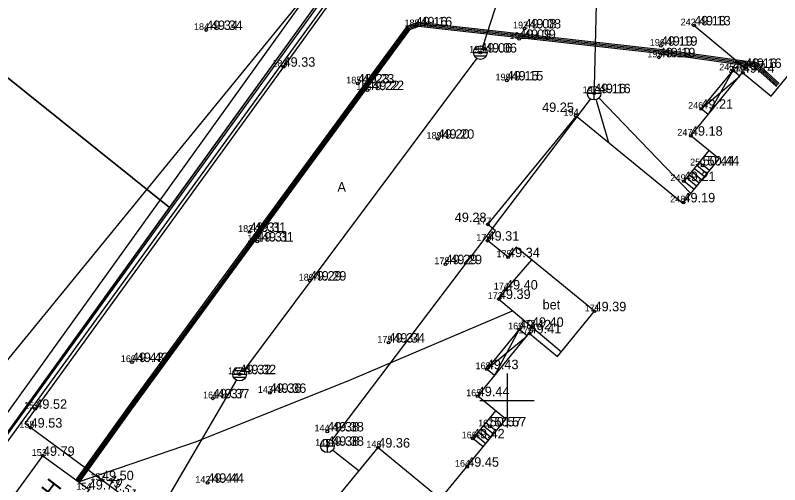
# Model space of a CAD drawing. Extents: x 640876 to 641418, y 6455595 to 6456085.
# Drawn here: x 641063.8 to 641120.1, y 6455893.8 to 6455928.4 of the extents above; entities that cross this region are included whole.
import ezdxf

# ---------------------------------------------------------------- set-up
doc = ezdxf.new("R2010")
doc.units = 0
for name, color, linetype in [('AED', 7, 'Continuous'), ('HOONE', 7, 'Continuous'), ('HOONEDET', 7, 'Continuous'), ('KKAEV', 7, 'Continuous'), ('KORGUS', 7, 'Continuous'), ('KTRASS', 7, 'Continuous'), ('MOOTKORG', 7, 'Continuous'), ('MOOTMPUNKT', 7, 'Continuous'), ('MOOTNR', 7, 'Continuous'), ('MOOTPIIR', 7, 'Continuous'), ('MPKAABEL', 7, 'Continuous'), ('PIIR', 7, 'Continuous'), ('PUU', 7, 'Continuous'), ('SKKAEV', 7, 'Continuous'), ('TEE', 7, 'Continuous'), ('VORK', 7, 'Continuous')]:
    doc.layers.add(name, color=color, linetype=linetype)

msp = doc.modelspace()

# ---------------------------------------------------------------- linework, layer by layer
at = {"layer": 'AED'}
for points in [[(641063.184, 6455882.915), (641067.225, 6455888.43), (641061.101, 6455894.64), (641102.569, 6455951.872), (641103.756, 6455952.954), (641094.123, 6455962.857), (641083.796, 6455973.39)], [(641113.788, 6455927.654), (641117.539, 6455924.523)]]:
    msp.add_lwpolyline(points, dxfattribs=at)
at = {"layer": 'HOONE'}
for p, q in [((641117.148, 6455923.919), (641116.636, 6455924.339)), ((641114.827, 6455921.087), (641114.315, 6455921.507)), ((641101.484, 6455904.77), (641100.904, 6455905.245)), ((641099.081, 6455901.837), (641098.503, 6455902.311)), ((641063.825, 6455893.209), (641065.802, 6455895.917))]:
    msp.add_line(p, q, dxfattribs=at)
for points in [[(641080.933, 6455884.842), (641090.509, 6455896.528), (641095.11, 6455892.757), (641099.913, 6455898.619), (641097.838, 6455900.32), (641101.638, 6455904.958), (641103.721, 6455903.251), (641106.446, 6455906.577), (641100.678, 6455911.304), (641100.074, 6455910.567), (641098.571, 6455911.798), (641099.157, 6455912.513), (641098.578, 6455912.988), (641105.114, 6455920.964), (641112.947, 6455914.545), (641115.628, 6455917.817), (641113.546, 6455919.523), (641117.357, 6455924.174), (641119.462, 6455922.449), (641148.038, 6455957.319)], [(641116.636, 6455924.339), (641114.315, 6455921.507)], [(641100.904, 6455905.245), (641098.503, 6455902.311)], [(641065.802, 6455895.917), (641069.2, 6455893.436), (641067.212, 6455890.725)]]:
    msp.add_lwpolyline(points, dxfattribs=at)
at = {"layer": 'HOONEDET'}
for p, q in [((641114.871, 6455918.437), (641113.022, 6455916.18)), ((641114.729, 6455916.72), (641113.972, 6455917.34)), ((641114.919, 6455916.952), (641114.162, 6455917.572)), ((641114.158, 6455916.024), (641113.402, 6455916.644)), ((641114.349, 6455916.256), (641113.592, 6455916.876)), ((641114.539, 6455916.488), (641113.782, 6455917.108)), ((641113.778, 6455915.56), (641113.022, 6455916.18)), ((641113.968, 6455915.792), (641113.212, 6455916.412)), ((641099.152, 6455899.243), (641097.483, 6455897.206)), ((641099.005, 6455897.51), (641098.243, 6455898.134)), ((641099.195, 6455897.742), (641098.434, 6455898.366)), ((641098.434, 6455896.814), (641097.673, 6455897.438)), ((641098.624, 6455897.046), (641097.863, 6455897.67)), ((641098.814, 6455897.278), (641098.053, 6455897.902)), ((641098.244, 6455896.582), (641097.483, 6455897.206))]:
    msp.add_line(p, q, dxfattribs=at)
for points in [[(641114.315, 6455921.507), (641117.148, 6455923.919)], [(641116.636, 6455924.339), (641114.827, 6455921.087)], [(641098.503, 6455902.311), (641101.484, 6455904.77)], [(641100.904, 6455905.245), (641099.081, 6455901.837)]]:
    msp.add_lwpolyline(points, dxfattribs=at)
at = {"layer": 'KKAEV'}
for p, q in [((641106.418, 6455922.157), (641106.418, 6455923.157)), ((641105.918, 6455922.657), (641106.918, 6455922.657)), ((641086.767, 6455896.162), (641086.767, 6455897.162)), ((641086.267, 6455896.662), (641087.267, 6455896.662))]:
    msp.add_line(p, q, dxfattribs=at)
for centre in [(641106.418, 6455922.657), (641086.767, 6455896.662)]:
    msp.add_circle(centre, 0.5, dxfattribs=at)
at = {"layer": 'KORGUS'}
for centre in [(641077.833, 6455927.316), (641093.266, 6455927.587), (641101.29, 6455927.431), (641113.788, 6455927.654), (641100.901, 6455926.656), (641111.34, 6455926.154), (641098.035, 6455925.649), (641111.186, 6455925.303), (641117.539, 6455924.523), (641089.001, 6455923.375), (641099.978, 6455923.596), (641089.722, 6455922.885), (641106.418, 6455922.657), (641105.062, 6455921.006), (641094.893, 6455919.299), (641114.416, 6455917.326), (641098.578, 6455912.988), (641081.035, 6455912.426), (641081.594, 6455911.72), (641095.469, 6455910.049), (641085.472, 6455908.84), (641091.271, 6455904.268), (641072.368, 6455902.834), (641080.295, 6455901.942), (641078.324, 6455900.158), (641082.516, 6455900.562), (641098.726, 6455898.089), (641086.759, 6455897.718), (641086.767, 6455896.662), (641090.509, 6455896.528), (641077.93, 6455893.935)]:
    msp.add_circle(centre, 0.1, dxfattribs=at)
at = {"layer": 'KTRASS'}
for points in [[(641107.089, 6455950.372), (641106.418, 6455923.157)], [(641104.971, 6455947.019), (641098.222, 6455926.122)], [(641090.812, 6455936.841), (641051.218, 6455888.362)], [(641097.769, 6455925.247), (641080.648, 6455902.296)], [(641106.114, 6455922.218), (641087.069, 6455897.06)], [(641106.771, 6455922.304), (641113.54, 6455915.269)], [(641106.562, 6455922.141), (641107.489, 6455919.018)], [(641080.069, 6455901.529), (641068.888, 6455882.4)], [(641087.159, 6455896.351), (641089.102, 6455894.81)]]:
    msp.add_lwpolyline(points, dxfattribs=at)
at = {"layer": 'MOOTMPUNKT'}
for centre in [(641077.833, 6455927.316), (641093.266, 6455927.587), (641101.29, 6455927.431), (641113.788, 6455927.654), (641100.901, 6455926.656), (641111.34, 6455926.154), (641098.035, 6455925.649), (641111.186, 6455925.303), (641083.533, 6455924.608), (641117.539, 6455924.523), (641116.636, 6455924.339), (641117.367, 6455924.166), (641089.001, 6455923.375), (641099.978, 6455923.596), (641089.722, 6455922.885), (641106.418, 6455922.657), (641114.315, 6455921.507), (641094.893, 6455919.299), (641113.546, 6455919.523), (641114.416, 6455917.326), (641113.022, 6455916.18), (641112.997, 6455914.606), (641081.035, 6455912.426), (641081.594, 6455911.72), (641098.56, 6455911.784), (641100.074, 6455910.567), (641095.469, 6455910.049), (641085.472, 6455908.84), (641099.924, 6455908.183), (641099.398, 6455907.484), (641106.446, 6455906.577), (641100.904, 6455905.245), (641101.832, 6455905.433), (641101.655, 6455904.944), (641091.271, 6455904.268), (641072.368, 6455902.834), (641080.295, 6455901.942), (641098.503, 6455902.311), (641078.324, 6455900.158), (641082.516, 6455900.562), (641097.838, 6455900.32), (641065.242, 6455899.388), (641064.893, 6455897.998), (641098.726, 6455898.089), (641086.759, 6455897.718), (641097.483, 6455897.206), (641086.767, 6455896.662), (641065.802, 6455895.917), (641097.062, 6455895.117), (641070.153, 6455894.127), (641077.93, 6455893.935)]:
    msp.add_circle(centre, 0.1, dxfattribs=at)
at = {"layer": 'MOOTPIIR'}
msp.add_lwpolyline([(641060.916, 6455895.936), (641100.061, 6455950.482), (641099.586, 6455952.159), (641069.132, 6455984.035), (641066.132, 6455988.623), (641076.463, 6456005.049), (641230.642, 6456010.048), (641237.36, 6455995.24), (641237.24, 6455992.81), (641236.258, 6455990.888), (641229.041, 6455971.315), (641203.026, 6455909.57), (641225.257, 6455906.847), (641239.512, 6455898.491), (641200.195, 6455851.697), (641192.016, 6455859.099), (641169.785, 6455829.138), (641192.025, 6455807.568), (641252.96, 6455758.075), (641231.388, 6455736.74), (641191.474, 6455775.975), (641152.419, 6455787.914), (641136.351, 6455788.307), (641049.066, 6455856.043)], dxfattribs=at)
at = {"layer": 'MPKAABEL'}
for points in [[(641120.05, 6455923.364), (641118.377, 6455924.888), (641111.449, 6455925.845), (641093.437, 6455927.88), (641092.621, 6455927.581), (641085.424, 6455917.777), (641078.97, 6455908.941), (641072.09, 6455899.53), (641068.3, 6455894.245), (641068.24, 6455894.16)], [(641119.983, 6455923.29), (641118.333, 6455924.793), (641111.436, 6455925.746), (641093.449, 6455927.778), (641092.683, 6455927.498), (641085.504, 6455917.718), (641079.051, 6455908.883), (641072.171, 6455899.471), (641068.381, 6455894.188), (641068.322, 6455894.102)], [(641119.915, 6455923.216), (641118.289, 6455924.698), (641111.424, 6455925.647), (641093.461, 6455927.676), (641092.746, 6455927.414), (641085.585, 6455917.659), (641079.131, 6455908.824), (641072.251, 6455899.413), (641068.463, 6455894.13), (641068.404, 6455894.045)], [(641119.848, 6455923.142), (641118.244, 6455924.604), (641111.411, 6455925.548), (641093.473, 6455927.574), (641092.809, 6455927.331), (641085.666, 6455917.6), (641079.212, 6455908.765), (641072.332, 6455899.354), (641068.545, 6455894.072), (641068.486, 6455893.988)], [(641068.436, 6455894.012), (641077.12, 6455896.97), (641088.52, 6455901.55), (641100.4, 6455906.6)]]:
    msp.add_lwpolyline(points, dxfattribs=at)
at = {"layer": 'PIIR'}
for points in [[(641074.95, 6455979.64), (641102.26, 6455951.82), (641075.14, 6455914.24), (641043, 6455940)], [(641098.62, 6455818.85), (641093.41, 6455823.22), (641084.65, 6455830.08), (641067.32, 6455843.61), (641055.55, 6455852.8), (641061.31, 6455859.9), (641051.68, 6455867.61), (641067, 6455888.54), (641060.97, 6455894.57), (641075.14, 6455914.24), (641087.11, 6455930.82), (641102.26, 6455951.82), (641160.91, 6455891.99), (641157.02, 6455885.66), (641139.49, 6455869), (641124.05, 6455849.81)], [(641043, 6455940), (641075.14, 6455914.24), (641060.97, 6455894.57), (641053.35, 6455902.7), (641047.4, 6455905.63), (641027.94, 6455921.32)]]:
    msp.add_lwpolyline(points, close=True, dxfattribs=at)
at = {"layer": 'PUU'}
msp.add_lwpolyline([(641102.791, 6455951.536), (641061.687, 6455894.955)], dxfattribs=at)
at = {"layer": 'SKKAEV'}
for p, q in [((641097.535, 6455925.649), (641098.535, 6455925.649)), ((641098.465, 6455925.899), (641097.605, 6455925.899)), ((641098.465, 6455925.399), (641097.605, 6455925.399)), ((641079.795, 6455901.942), (641080.795, 6455901.942)), ((641080.725, 6455902.192), (641079.865, 6455902.192)), ((641080.725, 6455901.692), (641079.865, 6455901.692))]:
    msp.add_line(p, q, dxfattribs=at)
for centre in [(641098.035, 6455925.649), (641080.295, 6455901.942)]:
    msp.add_circle(centre, 0.5, dxfattribs=at)
at = {"layer": 'TEE'}
for points in [[(641107.214, 6455949.459), (641106.639, 6455948.012), (641106.005, 6455947.351), (641102.383, 6455950.666), (641094.127, 6455939.27), (641083.533, 6455924.608), (641064.463, 6455898.315)], [(641101.8, 6455910.384), (641099.924, 6455908.183), (641099.398, 6455907.484), (641101.832, 6455905.433), (641104.002, 6455903.594)], [(641051.478, 6455865.64), (641052.941, 6455865.209), (641053.714, 6455865.333), (641054.327, 6455865.784), (641054.723, 6455866.329), (641065.034, 6455880.406), (641066.968, 6455883.06), (641072.377, 6455890.623), (641072.69, 6455891.334), (641072.584, 6455892.089), (641072.191, 6455892.636), (641070.153, 6455894.127), (641064.463, 6455898.315)]]:
    msp.add_lwpolyline(points, dxfattribs=at)
at = {"layer": 'VORK'}
for p, q in [((641100, 6455902), (641100, 6455898)), ((641098, 6455900), (641102, 6455900))]:
    msp.add_line(p, q, dxfattribs=at)

# ---------------------------------------------------------------- texts
at = {"layer": 'HOONE'}
msp.add_text('H', height=1.2, rotation=52.5447, dxfattribs=at).set_placement((641066.549, 6455892.721))
at = {"layer": 'KORGUS'}
for s, p in [('49.34', (641078.183, 6455927.316)), ('49.16', (641093.616, 6455927.587)), ('49.08', (641101.64, 6455927.431)), ('49.13', (641114.138, 6455927.654)), ('49.09', (641101.251, 6455926.656)), ('49.19', (641111.69, 6455926.154)), ('49.06', (641098.385, 6455925.649)), ('49.19', (641111.536, 6455925.303)), ('49.16', (641117.889, 6455924.523)), ('49.23', (641089.351, 6455923.375)), ('49.15', (641100.328, 6455923.596)), ('49.22', (641090.072, 6455922.885)), ('49.16', (641106.768, 6455922.657)), ('49.25', (641102.584, 6455921.269)), ('49.20', (641095.243, 6455919.299)), ('50.44', (641114.766, 6455917.326)), ('49.28', (641096.145, 6455913.154)), ('49.31', (641081.385, 6455912.426)), ('49.31', (641081.944, 6455911.72)), ('49.29', (641095.819, 6455910.049)), ('49.29', (641085.822, 6455908.84)), ('49.34', (641091.621, 6455904.268)), ('49.43', (641072.718, 6455902.834)), ('49.32', (641080.645, 6455901.942)), ('49.37', (641078.674, 6455900.158)), ('49.36', (641082.866, 6455900.562)), ('50.57', (641099.076, 6455898.089)), ('49.38', (641087.109, 6455897.718)), ('49.38', (641087.117, 6455896.662)), ('49.36', (641090.509, 6455896.528)), ('49.44', (641078.28, 6455893.935))]:
    msp.add_text(s, height=0.7, dxfattribs=at).set_placement(p)
msp.add_text('49.51', height=0.7, rotation=325.61, dxfattribs=at).set_placement((641070.516, 6455894.037))
at = {"layer": 'MOOTKORG'}
for s, p in [('49.34', (641077.833, 6455927.316)), ('49.16', (641093.266, 6455927.587)), ('49.08', (641101.29, 6455927.431)), ('49.13', (641113.788, 6455927.654)), ('49.09', (641100.901, 6455926.656)), ('49.19', (641111.34, 6455926.154)), ('49.06', (641098.035, 6455925.649)), ('49.19', (641111.186, 6455925.303)), ('49.33', (641083.533, 6455924.608)), ('49.17', (641116.636, 6455924.339)), ('49.16', (641117.539, 6455924.523)), ('49.14', (641117.367, 6455924.166)), ('49.23', (641089.001, 6455923.375)), ('49.15', (641099.978, 6455923.596)), ('49.22', (641089.722, 6455922.885)), ('49.16', (641106.418, 6455922.657)), ('49.21', (641114.315, 6455921.507)), ('49.20', (641094.893, 6455919.299)), ('49.18', (641113.546, 6455919.523)), ('50.44', (641114.416, 6455917.326)), ('49.21', (641113.022, 6455916.18)), ('49.19', (641112.997, 6455914.606)), ('49.31', (641081.035, 6455912.426)), ('49.31', (641081.594, 6455911.72)), ('49.31', (641098.56, 6455911.784)), ('49.34', (641100.074, 6455910.567)), ('49.29', (641095.469, 6455910.049)), ('49.29', (641085.472, 6455908.84)), ('49.40', (641099.924, 6455908.183)), ('49.39', (641099.398, 6455907.484)), ('49.39', (641106.446, 6455906.577)), ('49.42', (641100.904, 6455905.245)), ('49.40', (641101.832, 6455905.433)), ('49.41', (641101.655, 6455904.944)), ('49.34', (641091.271, 6455904.268)), ('49.43', (641072.368, 6455902.834)), ('49.32', (641080.295, 6455901.942)), ('49.43', (641098.503, 6455902.311)), ('49.37', (641078.324, 6455900.158)), ('49.36', (641082.516, 6455900.562)), ('49.44', (641097.838, 6455900.32)), ('49.52', (641065.242, 6455899.388)), ('49.53', (641064.893, 6455897.998)), ('50.57', (641098.726, 6455898.089)), ('49.38', (641086.759, 6455897.718)), ('49.42', (641097.483, 6455897.206)), ('49.38', (641086.767, 6455896.662)), ('49.79', (641065.802, 6455895.917)), ('49.45', (641097.062, 6455895.117)), ('49.50', (641070.153, 6455894.127)), ('49.44', (641077.93, 6455893.935)), ('49.77', (641069.175, 6455893.433))]:
    msp.add_text(s, height=0.7, dxfattribs=at).set_placement(p)
at = {"layer": 'MOOTNR'}
for s, p in [('188', (641092.441, 6455927.587)), ('192', (641100.44, 6455927.431)), ('242', (641112.788, 6455927.654)), ('184', (641076.933, 6455927.316)), ('191', (641100.177, 6455926.656)), ('193', (641097.21, 6455925.649)), ('196', (641110.515, 6455926.154)), ('195', (641110.336, 6455925.303)), ('183', (641082.708, 6455924.608)), ('243', (641116.564, 6455924.523)), ('245', (641115.636, 6455924.339)), ('244', (641116.317, 6455924.166)), ('190', (641099.153, 6455923.596)), ('185', (641088.151, 6455923.375)), ('186', (641088.897, 6455922.885)), ('197', (641105.568, 6455922.657)), ('246', (641113.34, 6455921.507)), ('194', (641104.162, 6455921.006)), ('247', (641112.546, 6455919.523)), ('189', (641094.069, 6455919.299)), ('250', (641113.491, 6455917.326)), ('249', (641112.047, 6455916.18)), ('248', (641112.022, 6455914.606)), ('177', (641097.728, 6455912.988)), ('182', (641080.185, 6455912.426)), ('181', (641080.869, 6455911.72)), ('176', (641097.735, 6455911.784)), ('175', (641099.224, 6455910.567)), ('178', (641094.644, 6455910.049)), ('180', (641084.648, 6455908.84)), ('174', (641099.024, 6455908.183)), ('173', (641098.573, 6455907.484)), ('171', (641105.721, 6455906.577)), ('172', (641100.982, 6455905.433)), ('169', (641100.079, 6455905.245)), ('170', (641100.83, 6455904.944)), ('179', (641090.446, 6455904.268)), ('160', (641071.543, 6455902.834)), ('168', (641097.678, 6455902.311)), ('162', (641079.445, 6455901.942)), ('143', (641081.641, 6455900.562)), ('165', (641096.988, 6455900.32)), ('161', (641077.599, 6455900.158)), ('159', (641064.417, 6455899.388)), ('167', (641097.876, 6455898.089)), ('158', (641064.068, 6455897.998)), ('144', (641085.809, 6455897.718)), ('166', (641096.658, 6455897.206)), ('145', (641085.867, 6455896.662)), ('146', (641089.634, 6455896.528)), ('153', (641064.977, 6455895.917)), ('164', (641096.162, 6455895.117)), ('152', (641069.303, 6455894.127)), ('142', (641077.03, 6455893.935)), ('154', (641068.275, 6455893.433))]:
    msp.add_text(s, height=0.5, dxfattribs=at).set_placement(p)
at = {"layer": 'TEE'}
for s, p in [('A', (641087.505, 6455915.399)), ('bet', (641102.621, 6455906.718))]:
    msp.add_text(s, height=0.7, dxfattribs=at).set_placement(p)

doc.saveas('drawing.dxf')
